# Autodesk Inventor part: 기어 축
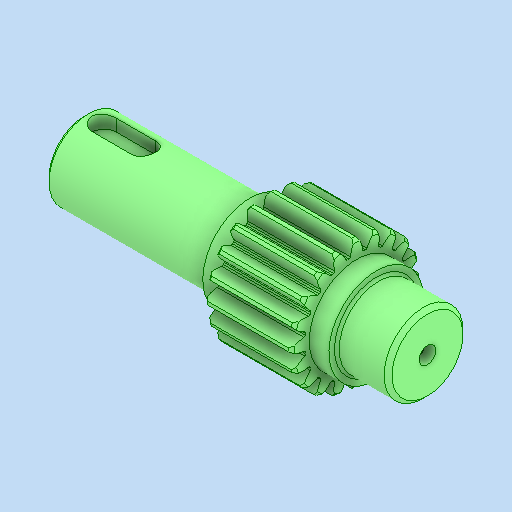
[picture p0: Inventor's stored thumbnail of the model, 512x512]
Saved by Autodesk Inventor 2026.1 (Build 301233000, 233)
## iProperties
Created: 2025-11
Part Number: 기어 축
Material: 강철, 합금
Document SubType Name: Modeling
Designer: PC-30
Density: 7.73 g/cm^3
Appearance: 기본값
Author: jhkim
Sending System: Autodesk Inventor 2026
Preprocessor: ST-DEVELOPER v20.1
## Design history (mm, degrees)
feature "솔리드1"
node "솔리드2"
